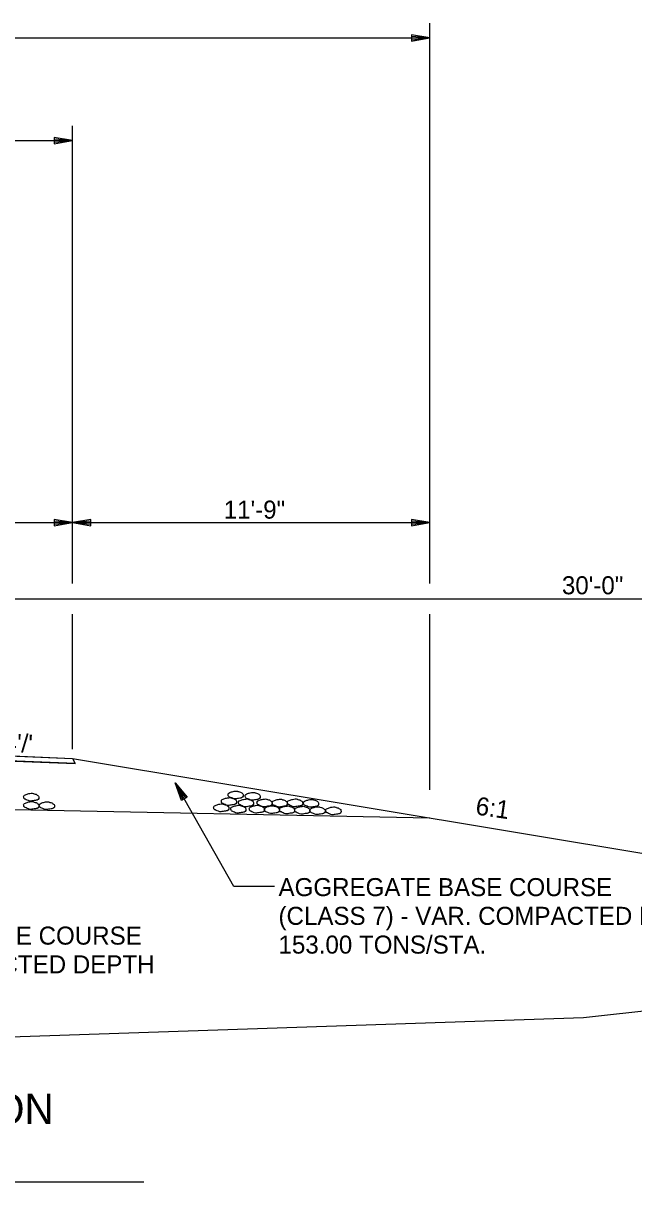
# Model space of a CAD drawing. Extents: x 1734743 to 1735935, y 759845 to 763831.
# Drawn here: x 1735769.43 to 1735789.41, y 762724.79 to 762762.69 of the extents above; entities that cross this region are included whole.
import ezdxf

# ---------------------------------------------------------------- set-up
doc = ezdxf.new("R2010")
doc.units = 0
for name, color, linetype in [('1', 7, 'Continuous'), ('19', 7, 'Continuous'), ('Level 1', 7, 'Continuous'), ('R_Prop Surface', 7, 'Continuous')]:
    doc.layers.add(name, color=color, linetype=linetype)

# ---------------------------------------------------------------- blocks, each defined once
blk = doc.blocks.new('ROCKS')
at = {"layer": '1'}
blk.add_spline([(0.013, 0.06), (0.053, 0.053), (0.107, 0.033), (0.133, 0.013), (0.133, -0.007), (0.12, -0.033), (0.107, -0.04), (0.073, -0.053), (0.033, -0.067), (0.013, -0.067), (-0.02, -0.06), (-0.06, -0.053), (-0.087, -0.047), (-0.113, -0.02), (-0.113, -0.007), (-0.107, 0.02), (-0.087, 0.033), (-0.067, 0.047), (-0.033, 0.053), (-0.02, 0.06), (0.013, 0.06)], degree=3, dxfattribs=at)

msp = doc.modelspace()

# ---------------------------------------------------------------- linework, layer by layer
at = {"layer": '19'}
for p, q in [((1735782.728, 762744.366), (1735782.728, 762762.693)), ((1735782.128, 762762.313), (1735782.128, 762762.103)), ((1735782.728, 762762.208), (1735782.128, 762762.313)), ((1735782.568, 762762.223), (1735782.128, 762762.258)), ((1735734.086, 762762.208), (1735782.728, 762762.208)), ((1735782.128, 762762.103), (1735782.728, 762762.208)), ((1735782.128, 762762.153), (1735782.568, 762762.193)), ((1735771.047, 762746.901), (1735771.046, 762759.337)), ((1735746.047, 762758.852), (1735771.046, 762758.852)), ((1735770.446, 762758.957), (1735770.446, 762758.747)), ((1735771.046, 762758.852), (1735770.446, 762758.957)), ((1735770.886, 762758.867), (1735770.446, 762758.902)), ((1735770.446, 762758.747), (1735771.046, 762758.852)), ((1735770.446, 762758.797), (1735770.886, 762758.837)), ((1735771.046, 762744.366), (1735771.047, 762746.901)), ((1735765.047, 762746.358), (1735771.047, 762746.357)), ((1735770.447, 762746.462), (1735770.447, 762746.252)), ((1735771.047, 762746.357), (1735770.447, 762746.462)), ((1735770.887, 762746.372), (1735770.447, 762746.407)), ((1735770.447, 762746.252), (1735771.047, 762746.357)), ((1735770.447, 762746.302), (1735770.887, 762746.342)), ((1735771.647, 762746.462), (1735771.047, 762746.357)), ((1735771.047, 762746.357), (1735782.728, 762746.356)), ((1735771.047, 762746.357), (1735771.647, 762746.252)), ((1735771.647, 762746.407), (1735771.207, 762746.372)), ((1735771.207, 762746.342), (1735771.647, 762746.302)), ((1735771.647, 762746.252), (1735771.647, 762746.462)), ((1735782.128, 762746.461), (1735782.128, 762746.251)), ((1735782.728, 762746.356), (1735782.128, 762746.461)), ((1735782.568, 762746.371), (1735782.128, 762746.406)), ((1735782.128, 762746.251), (1735782.728, 762746.356)), ((1735782.128, 762746.301), (1735782.568, 762746.341)), ((1735765.046, 762743.867), (1735795.041, 762743.864)), ((1735765.046, 762743.867), (1735795.041, 762743.864)), ((1735771.046, 762738.946), (1735771.046, 762743.366)), ((1735782.728, 762737.613), (1735782.728, 762743.366)), ((1735765.046, 762738.887), (1735771.046, 762738.646)), ((1735765.131, 762738.716), (1735771.131, 762738.476)), ((1735771.046, 762738.646), (1735795.046, 762734.644)), ((1735776.319, 762734.45), (1735774.406, 762737.843)), ((1735774.61, 762737.269), (1735774.406, 762737.843)), ((1735774.406, 762737.843), (1735774.792, 762737.371)), ((1735774.648, 762737.295), (1735774.472, 762737.695)), ((1735774.493, 762737.71), (1735774.743, 762737.349)), ((1735774.792, 762737.371), (1735774.61, 762737.269)), ((1735767.034, 762737.013), (1735782.728, 762736.698)), ((1735777.65, 762734.45), (1735776.319, 762734.45)), ((1735745.216, 762724.796), (1735773.379, 762724.794))]:
    msp.add_line(p, q, dxfattribs=at)
for points in [[(1735771.131, 762738.476), (1735765.131, 762738.716), (1735750.047, 762739.021), (1735749.961, 762739.018), (1735749.961, 762739.018), (1735745.961, 762738.858), (1735746.046, 762739.028), (1735746.046, 762739.028), (1735750.046, 762739.188), (1735765.046, 762738.887), (1735771.046, 762738.646), (1735771.046, 762738.646), (1735771.131, 762738.476), (1735771.131, 762738.476), (1735771.131, 762738.476)], [(1735737.574, 762730.516), (1735737.825, 762730.509), (1735746.995, 762731.188), (1735752.775, 762728.468), (1735767.375, 762729.486), (1735787.755, 762730.165), (1735799.985, 762731.524), (1735809.495, 762729.823), (1735820.81, 762732.261), (1735822.413, 762731.949)]]:
    msp.add_lwpolyline(points, dxfattribs=at)
at = {"layer": 'R_Prop Surface'}
msp.add_line((1735771.046, 762738.646), (1735771.131, 762738.476), dxfattribs=at)

# ---------------------------------------------------------------- block references
at = {"layer": 'Level 1', "xscale": 2.011654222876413}
for p, yscale, rotation in [((1735769.713, 762737.381), -2.0116542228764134, 177.95871721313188), ((1735769.713, 762737.11), -2.0116542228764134, 177.95871721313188), ((1735776.182, 762737.238), -2.011654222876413, 178.17361855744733), ((1735776.4, 762737.452), -2.011654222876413, 178.17361855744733), ((1735776.74, 762737.194), -2.011654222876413, 178.17361855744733), ((1735776.957, 762737.408), -2.011654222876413, 178.17361855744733), ((1735777.348, 762737.194), -2.011654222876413, 178.17361855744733), ((1735777.841, 762737.187), -2.011654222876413, 178.17361855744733), ((1735778.347, 762737.195), -2.011654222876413, 178.17361855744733), ((1735778.868, 762737.179), -2.011654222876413, 178.17361855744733), ((1735770.226, 762737.102), -2.0116542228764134, 177.95871721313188), ((1735775.93, 762737.033), -2.011654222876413, 178.17361855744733), ((1735776.488, 762736.988), -2.011654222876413, 178.17361855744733), ((1735777.096, 762736.988), -2.011654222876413, 178.17361855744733), ((1735777.587, 762736.972), -2.011654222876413, 178.17361855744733), ((1735778.083, 762736.965), -2.011654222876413, 178.17361855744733), ((1735778.579, 762736.954), -2.011654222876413, 178.17361855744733), ((1735779.079, 762736.94), -2.011654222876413, 178.17361855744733), ((1735779.6, 762736.934), -2.011654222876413, 178.17361855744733)]:
    msp.add_blockref('ROCKS', p, dxfattribs=dict(at, yscale=yscale, rotation=rotation))

# ---------------------------------------------------------------- texts
at = {"layer": '19'}
for s, height, rotation, p in [('11\'-9"', 0.59, 359.9954, (1735775.99, 762746.486)), ('30\'-0"', 0.59, 359.9954, (1735787.053, 762744.012)), ("0.04'/'", 0.59, 357.3841, (1735767.676, 762738.923)), ('6:1', 0.59, 351.855, (1735784.205, 762736.812)), ('AGGREGATE BASE COURSE', 0.59001, 360, (1735777.782, 762734.139)), ('(CLASS 7) - VAR. COMPACTED DEPTH', 0.59001, 360, (1735777.782, 762733.199)), ('153.00 TONS/STA.', 0.59001, 360, (1735777.782, 762732.259)), ('SINGLE LANE RAMP TYPICAL SECTION', 0.98999, 359.9954, (1735745.416, 762726.685))]:
    msp.add_text(s, height=height, rotation=rotation, dxfattribs=at).set_placement(p)
for s, p in [('15\'-0"AGGREGATE BASE COURSE', (1735760.383, 762732.553)), ('(CLASS 7) - 7" COMPACTED DEPTH', (1735760.383, 762731.613))]:
    msp.add_text(s, height=0.59001, dxfattribs=at).set_placement(p)

doc.saveas('drawing.dxf')
